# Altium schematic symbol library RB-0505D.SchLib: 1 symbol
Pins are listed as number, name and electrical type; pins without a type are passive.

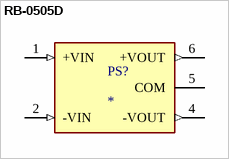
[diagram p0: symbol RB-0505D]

## RB-0505D
designator PS?
1W DC/DC-Converter 'ECONOLINE' SIP7 1kV unreg; MF: Recom Power; MP: RB-0505D
footprint RB-0505D
pins: 1 +VIN (in), 2 -VIN (in), 4 -VOUT (out), 5 COM (power), 6 +VOUT (out)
